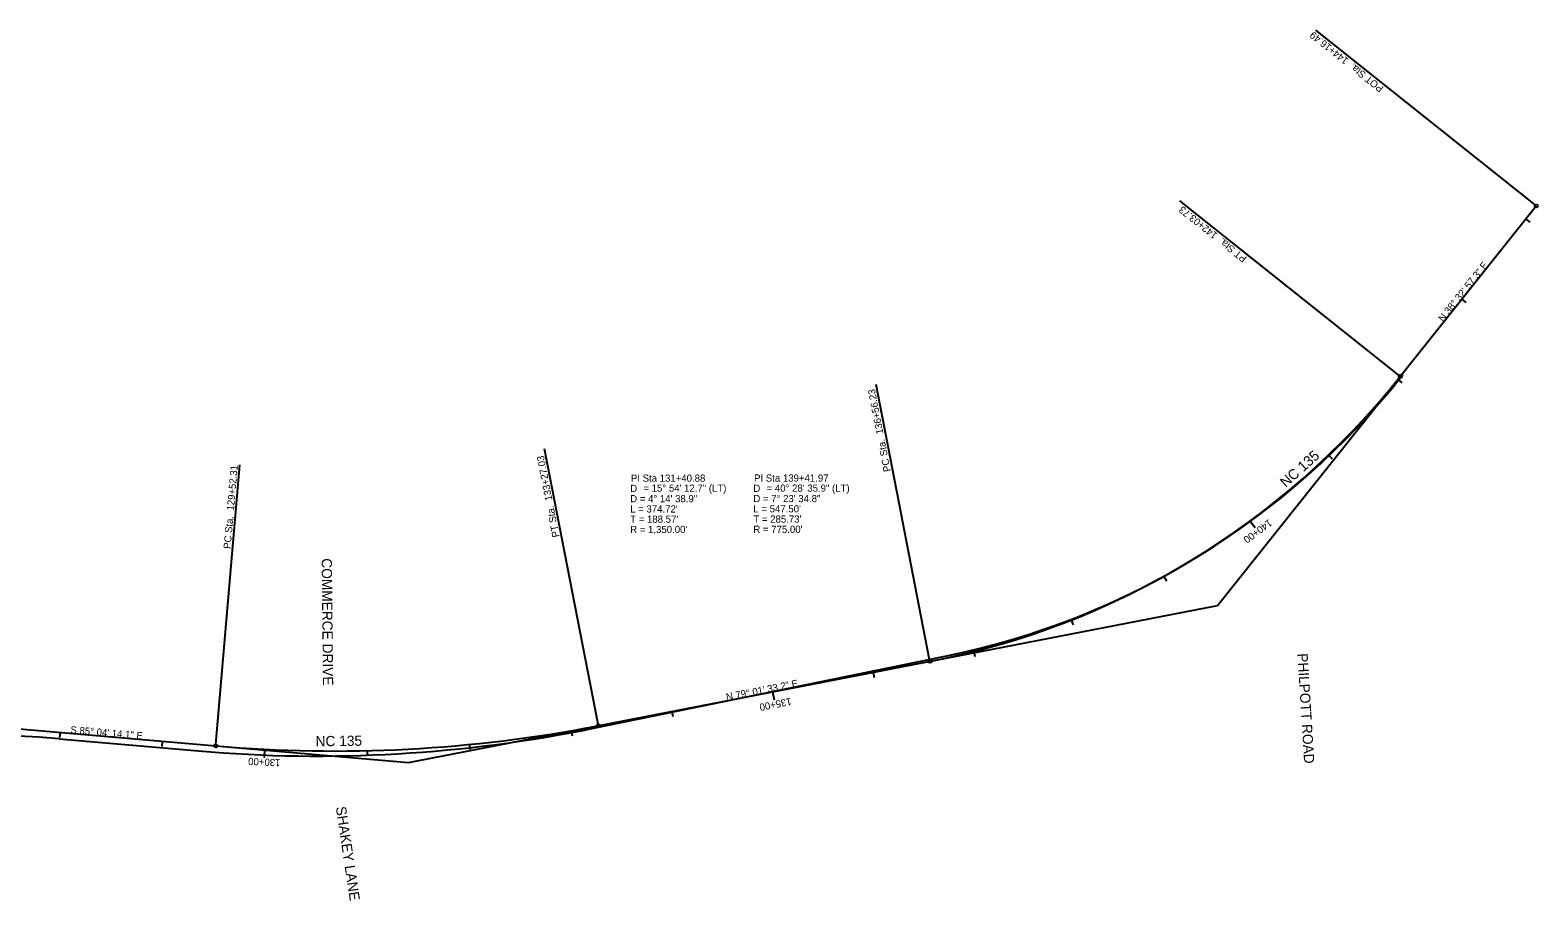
# Model space of a CAD drawing. Extents: x 1722038 to 1726172, y 967033 to 975427.
# Drawn here: x 1724702 to 1726172, y 971949 to 972798 of the extents above; entities that cross this region are included whole.
import ezdxf

# ---------------------------------------------------------------- set-up
doc = ezdxf.new("R2010")
doc.units = 0
for name, color, linetype in [('Prop Horizontal Alignment', 7, 'Continuous'), ('Prop Horizontal Alignment Curve and Spiral Data', 7, 'Continuous'), ('Prop Horizontal Alignment Direction Label', 7, 'Continuous'), ('Prop Horizontal Alignment Station Label', 7, 'Continuous'), ('Prop Horizontal Alignment Tick Label', 7, 'Continuous'), ('Prop Horizontal Alignment Tick Large', 7, 'Continuous'), ('Prop Horizontal Alignment Tick Small', 7, 'Continuous')]:
    doc.layers.add(name, color=color, linetype=linetype)

msp = doc.modelspace()

# ---------------------------------------------------------------- linework, layer by layer
at = {"layer": 'Prop Horizontal Alignment'}
for p, q in [((1725859.5, 972237.2), (1726170.1, 972627)), ((1725070.7, 972084.2), (1725859.5, 972237.2)), ((1725252.6, 972117.9), (1725594, 972187.8)), ((1724317.8, 972149.1), (1725070.7, 972084.2)), ((1724730.1, 972107.3), (1724865.9, 972095.5))]:
    msp.add_line(p, q, dxfattribs=at)
for centre, radius, start, end in [((1725431.4, 972943.6), 775, 280.9741, 321.4507), ((1725440.8, 972936.2), 763.9, 281.5678, 321.6733), ((1724982.3, 973438.6), 1348.1, 265.0497, 281.5678), ((1724998.8, 973445.4), 1350, 265.0706, 280.9741), ((1724635.9, 971020), 1091.3, 85.0497, 118.2178)]:
    msp.add_arc(centre, radius, start, end, dxfattribs=at)
at = {"layer": 'Prop Horizontal Alignment Station Label'}
for p, q in [((1726169, 972627.9), (1725955.1, 972798.4)), ((1726036.4, 972461.6), (1725822.5, 972632)), ((1725578.7, 972184.2), (1725526.6, 972452.7)), ((1725255.5, 972121.6), (1725203.4, 972390.1)), ((1724882.9, 972101.9), (1724906.4, 972374.4))]:
    msp.add_line(p, q, dxfattribs=at)
for centre in [(1726170.1, 972627), (1726037.5, 972460.6), (1725579, 972182.8), (1725255.8, 972120.1), (1724882.8, 972100.4)]:
    msp.add_circle(centre, 1.5, dxfattribs=at)
at = {"layer": 'Prop Horizontal Alignment Tick Large'}
for p, q in [((1725891.2, 972319.7), (1725896, 972313.3)), ((1725425.6, 972153), (1725427.1, 972145.2)), ((1724930.4, 972097.1), (1724930, 972089.1))]:
    msp.add_line(p, q, dxfattribs=at)
at = {"layer": 'Prop Horizontal Alignment Tick Small'}
for p, q in [((1726159.8, 972614.1), (1726163.8, 972611)), ((1726097.5, 972535.9), (1726101.4, 972532.8)), ((1726035.2, 972457.7), (1726039.1, 972454.6)), ((1725967.7, 972384.1), (1725971.1, 972380.4)), ((1725807.1, 972265.7), (1725809.5, 972261.4)), ((1725716.8, 972223), (1725718.6, 972218.4)), ((1725621.7, 972192.3), (1725622.9, 972187.5)), ((1725523.8, 972172.1), (1725524.7, 972167.1)), ((1725327.4, 972134), (1725328.4, 972129.1)), ((1724731, 972113.5), (1724730.6, 972108.5)), ((1725229.2, 972115.2), (1725230.1, 972110.3)), ((1724830.7, 972104.9), (1724830.2, 972099.9)), ((1725130.1, 972101.8), (1725130.6, 972096.8)), ((1725030.3, 972095.8), (1725030.4, 972090.8))]:
    msp.add_line(p, q, dxfattribs=at)

# ---------------------------------------------------------------- texts
at = {"layer": 'Prop Horizontal Alignment Curve and Spiral Data'}
for s, p in [('PI Sta 131+40.88', (1725287.5, 972358)), ('PI Sta 139+41.97', (1725407.6, 972358.1)), ('D', (1725286.8, 972348)), ('= 15%%d 54\' 12.7" (LT)', (1725299.7, 972348.3)), ('D', (1725406.9, 972348.1)), ('= 40%%d 28\' 35.9" (LT)', (1725419.8, 972348.3)), ('D = 4%%d 14\' 38.9"', (1725286.8, 972338)), ("L = 374.72'", (1725286.8, 972328)), ('D = 7%%d 23\' 34.8"', (1725406.9, 972338.1)), ("L = 547.50'", (1725406.9, 972328.1)), ("T = 188.57'", (1725286.8, 972318)), ("T = 285.73'", (1725406.9, 972318.1)), ("R = 1,350.00'", (1725286.8, 972308)), ("R = 775.00'", (1725406.9, 972308.1))]:
    msp.add_text(s, height=7, dxfattribs=at).set_placement(p)
at = {"layer": 'Prop Horizontal Alignment Direction Label'}
for s, rotation, p in [('N 38%%d 32\' 57.3" E', 51.4507, (1726079.3, 972513.4)), ('N 79%%d 01\' 33.2" E', 10.9741, (1725381, 972144.6)), ('S 85%%d 04\' 14.1" E', 355.0706, (1724740.9, 972112.8))]:
    msp.add_text(s, height=7, rotation=rotation, dxfattribs=at).set_placement(p)
at = {"layer": 'Prop Horizontal Alignment Station Label'}
for s, rotation, p in [('POT Sta.  144+16.49', 141.4507, (1726021.8, 972742.6)), ('PT Sta.  142+03.73', 141.4507, (1725888.5, 972576.8)), ('PC Sta.  136+56.23', 100.9741, (1725540.9, 972368.4)), ('PT Sta.  133+27.03', 100.9741, (1725218, 972304.5)), ('PC Sta.  129+52.31', 85.0706, (1724897.3, 972292.3))]:
    msp.add_text(s, height=7, rotation=rotation, dxfattribs=at).set_placement(p)
at = {"layer": 'Prop Horizontal Alignment Tick Label'}
for s, height, rotation, p in [('NC 135', 10, 41.7023, (1725925.8, 972351.9)), ('140+00', 7, 216.3889, (1725909.3, 972321.8)), ('COMMERCE DRIVE', 10, 270.6126, (1724986, 972283.3)), ('PHILPOTT ROAD', 10, 273.5531, (1725937.2, 972190.4)), ('135+00', 7, 190.9741, (1725443.3, 972147.3)), ('NC 135', 10, 0.833, (1724980.2, 972099.9)), ('130+00', 7, 177.0946, (1724946.1, 972087.3)), ('SHAKEY LANE', 10, 278.5535, (1724999.8, 972040.6))]:
    msp.add_text(s, height=height, rotation=rotation, dxfattribs=at).set_placement(p)

doc.saveas('drawing.dxf')
